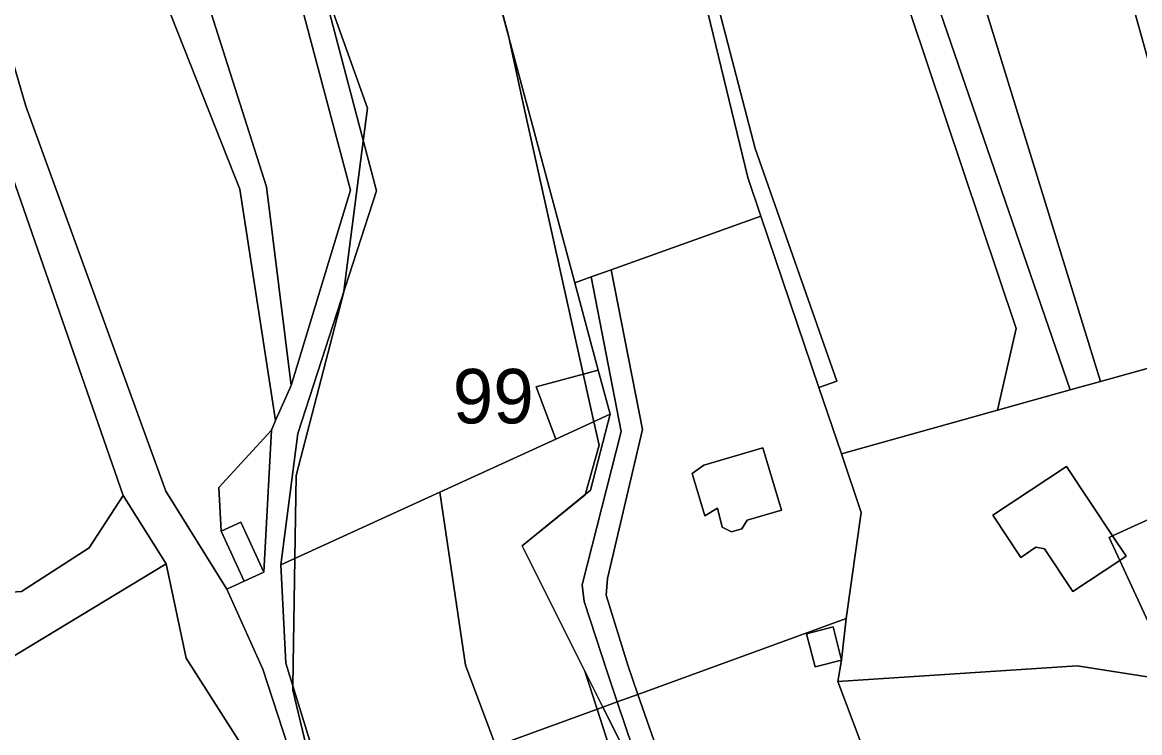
# Model space of a CAD drawing. Extents: x -502026 to -497664, y -1143484 to -1138019.
# Drawn here: x -498725.7 to -498561.6, y -1140123.3 to -1140018.9 of the extents above; entities that cross this region are included whole.
import ezdxf

# ---------------------------------------------------------------- set-up
doc = ezdxf.new("R2010")
doc.units = 0
for name, color, linetype in [('25', 7, 'Continuous'), ('31', 7, 'Continuous'), ('37', 7, 'Continuous'), ('43', 7, 'Continuous'), ('55', 7, 'Continuous'), ('62', 7, 'Continuous'), ('7', 7, 'Continuous')]:
    doc.layers.add(name, color=color, linetype=linetype)

msp = doc.modelspace()

# ---------------------------------------------------------------- linework, layer by layer
at = {"layer": '25'}
for points in [[(-498712.25, -1139972.61), (-498689.86, -1140043.06), (-498686.21, -1140072.24), (-498688.51, -1140077.4), (-498693.76, -1140043.4), (-498707.51, -1140008.59), (-498714.46, -1139986.58), (-498717.98, -1139975.42), (-498712.79, -1139970.57)], [(-498727.94, -1140039.32), (-498751.07, -1140049.89), (-498739.06, -1140080.19), (-498736.41, -1140103.23), (-498725.81, -1140102.53), (-498715.9, -1140096.1), (-498710.91, -1140088.4), (-498704.59, -1140098.48), (-498735.04, -1140116.85), (-498736.55, -1140110.23), (-498751.07, -1140095.02), (-498750.81, -1140092.61), (-498749.67, -1140082.31), (-498743.36, -1140080.78), (-498755.47, -1140046.68), (-498756.33, -1140044.28), (-498730, -1140033.28)], [(-498710.91, -1140088.4), (-498715.9, -1140096.1), (-498725.81, -1140102.53), (-498736.41, -1140103.23), (-498739.06, -1140080.19), (-498751.07, -1140049.89), (-498727.94, -1140039.32)]]:
    msp.add_lwpolyline(points, close=True, dxfattribs=at)
for points in [[(-498547.05, -1140117.17), (-498570.8, -1140113.45), (-498605.95, -1140115.74), (-498605.41, -1140112.59), (-498604.75, -1140106.51), (-498602.51, -1140090.92), (-498605.43, -1140082.3), (-498582.52, -1140075.89), (-498571.82, -1140072.9), (-498567.4, -1140071.66), (-498547.17, -1140066.02)], [(-498559.18, -1140091.38), (-498565.61, -1140094.35), (-498572.36, -1140084.16), (-498583.19, -1140091.32), (-498579.1, -1140097.52), (-498576.88, -1140096.03), (-498575.62, -1140096.27), (-498571.46, -1140102.52), (-498564.56, -1140097.96), (-498559.5, -1140108.89)]]:
    msp.add_lwpolyline(points, dxfattribs=at)
at = {"layer": '31'}
msp.add_lwpolyline([(-498674.75, -1140195.99), (-498680.38, -1140198.74), (-498683.99, -1140191.33), (-498699.81, -1140199.06), (-498713.39, -1140173.67), (-498729.52, -1140136.87), (-498735.04, -1140116.85), (-498704.59, -1140098.48), (-498701.66, -1140112.3), (-498691.1, -1140128.83), (-498682.3, -1140153.95)], close=True, dxfattribs=at)
at = {"layer": '37'}
for points in [[(-498580.7, -1139904.91), (-498574.32, -1139926.66), (-498559.71, -1139982.7), (-498534.68, -1140067.99), (-498523.51, -1140099.19), (-498525.46, -1140099.67), (-498503.51, -1140161.05), (-498513.07, -1140159.27), (-498523.05, -1140142.79), (-498532.36, -1140111.9), (-498543.21, -1140078.75), (-498547.17, -1140066.02), (-498557.89, -1140033.39), (-498577.39, -1139963.52), (-498584.01, -1139942.13), (-498590.01, -1139920.48), (-498609.44, -1139845.64), (-498615.65, -1139814.41), (-498623.41, -1139785.38), (-498626.05, -1139772.41), (-498623.42, -1139762.03), (-498619.31, -1139757.84), (-498592.84, -1139833.58), (-498587.99, -1139880.06)], [(-498590.01, -1139920.48), (-498584.01, -1139942.13), (-498596.15, -1139928.3), (-498610.66, -1139931.23), (-498567.4, -1140071.66), (-498571.82, -1140072.9), (-498605.77, -1139974.16), (-498614.84, -1139940.05), (-498617.87, -1139937.49), (-498639.91, -1139872.46), (-498644.26, -1139843.3), (-498642.74, -1139830.04), (-498633.26, -1139854.5), (-498613.18, -1139925.51)], [(-498672.63, -1139848.98), (-498663.63, -1139876.66), (-498638.19, -1139954.89), (-498627.01, -1140009.3), (-498619.17, -1140041.68), (-498617.24, -1140047.37), (-498639.25, -1140055.25), (-498642.18, -1140056.3), (-498644.57, -1140057.16), (-498671.08, -1139958.4), (-498663.04, -1139937.41), (-498672.5, -1139909.81), (-498683.31, -1139899.39), (-498702.08, -1139848.49), (-498674.5, -1139843.51)], [(-498582.52, -1140075.89), (-498605.43, -1140082.3), (-498608.73, -1140072.55), (-498606.09, -1140071.61), (-498618.07, -1140037.42), (-498625.5, -1140008.98), (-498627.01, -1140009.3), (-498638.19, -1139954.89), (-498663.63, -1139876.66), (-498644.2, -1139870.82), (-498621.06, -1139939.57), (-498617.75, -1139942.21), (-498605.69, -1139986.46), (-498579.78, -1140063.88)], [(-498584.01, -1139942.13), (-498577.39, -1139963.52), (-498557.89, -1140033.39), (-498547.17, -1140066.02), (-498567.4, -1140071.66), (-498610.66, -1139931.23), (-498596.15, -1139928.3)], [(-498608.73, -1140072.55), (-498605.43, -1140082.3), (-498602.51, -1140090.92), (-498604.75, -1140106.51), (-498635.31, -1140117.65), (-498636.81, -1140113.33), (-498639.97, -1140103.05), (-498639.77, -1140100.6), (-498634.64, -1140078.71), (-498639.25, -1140055.25), (-498617.24, -1140047.37)], [(-498638.34, -1140118.75), (-498640.44, -1140119.52), (-498652.29, -1140095.81), (-498642.28, -1140087.64), (-498639.38, -1140076.48), (-498641.13, -1140069.98), (-498644.57, -1140057.16), (-498642.18, -1140056.3), (-498637.78, -1140079.01), (-498643.5, -1140101.56), (-498643.21, -1140103.98), (-498639.8, -1140114.46)], [(-498635.31, -1140117.65), (-498638.34, -1140118.75), (-498639.8, -1140114.46), (-498643.21, -1140103.98), (-498643.5, -1140101.56), (-498637.78, -1140079.01), (-498642.18, -1140056.3), (-498639.25, -1140055.25), (-498634.64, -1140078.71), (-498639.77, -1140100.6), (-498639.97, -1140103.05), (-498636.81, -1140113.33)], [(-498616.95, -1140081.43), (-498625.63, -1140083.96), (-498627.33, -1140085.19), (-498625.5, -1140091.39), (-498623.62, -1140090.3), (-498622.92, -1140093.07), (-498621.56, -1140093.77), (-498620.03, -1140093.33), (-498619.26, -1140092.06), (-498614.24, -1140090.59)], [(-498605.41, -1140112.59), (-498606.65, -1140107.71), (-498610.56, -1140108.73), (-498609.27, -1140113.61), (-498605.41, -1140112.59), (-498605.95, -1140115.74), (-498598.07, -1140136.66), (-498625.77, -1140147.79), (-498626.21, -1140147.97), (-498626.85, -1140145.7), (-498630.48, -1140131.52), (-498633.99, -1140121.45), (-498635.31, -1140117.65), (-498604.75, -1140106.51)], [(-498547.05, -1140117.17), (-498544.9, -1140123.19), (-498553.52, -1140120.93), (-498556.27, -1140131.07), (-498546.77, -1140133.65), (-498545.8, -1140129.93), (-498543.71, -1140130.48), (-498542.85, -1140127.18), (-498544.93, -1140126.63), (-498544.09, -1140123.4), (-498544.9, -1140123.19), (-498532.69, -1140118.83), (-498526.12, -1140142.06), (-498518.02, -1140162.88), (-498520.94, -1140164.17), (-498530.79, -1140144.21), (-498571.63, -1140162.6), (-498560.56, -1140182.88), (-498581.76, -1140187.79), (-498588.51, -1140166.89), (-498590.01, -1140162.02), (-498598.07, -1140136.66), (-498605.95, -1140115.74), (-498570.8, -1140113.45)], [(-498632.83, -1140135.95), (-498634.63, -1140131.14), (-498640.44, -1140119.52), (-498638.34, -1140118.75), (-498637.06, -1140122.49), (-498633.7, -1140132.45)], [(-498626.21, -1140147.97), (-498629.39, -1140149.25), (-498630.23, -1140146.34), (-498630.69, -1140144.51), (-498630.44, -1140142.31), (-498632.83, -1140135.95), (-498633.7, -1140132.45), (-498637.06, -1140122.49), (-498638.34, -1140118.75), (-498635.31, -1140117.65), (-498633.99, -1140121.45), (-498630.48, -1140131.52), (-498626.85, -1140145.7)]]:
    msp.add_lwpolyline(points, close=True, dxfattribs=at)
at = {"layer": '43'}
msp.add_lwpolyline([(-498671.08, -1139958.4), (-498644.57, -1140057.16), (-498641.13, -1140069.98), (-498650.24, -1140072.45), (-498647.34, -1140080.12), (-498664.39, -1140087.93), (-498687.74, -1140098.62), (-498685.24, -1140079.33), (-498673.72, -1140043.63), (-498689.86, -1139982.26)], dxfattribs=at)
msp.add_lwpolyline([(-498639.38, -1140076.48), (-498647.34, -1140080.12), (-498650.24, -1140072.45), (-498641.13, -1140069.98)], close=True, dxfattribs=at)
at = {"layer": '55'}
for points in [[(-498605.77, -1139974.16), (-498571.82, -1140072.9), (-498582.52, -1140075.89), (-498579.78, -1140063.88), (-498605.69, -1139986.46)], [(-498736.26, -1139993.31), (-498725.17, -1140031.2), (-498704.65, -1140087.78), (-498695.68, -1140102.2), (-498690.38, -1140113.94), (-498677.05, -1140154.76), (-498679.25, -1140155.67), (-498672.29, -1140195.45), (-498674.75, -1140195.99), (-498682.3, -1140153.95), (-498691.1, -1140128.83), (-498701.66, -1140112.3), (-498704.59, -1140098.48), (-498710.91, -1140088.4), (-498727.94, -1140039.32), (-498730, -1140033.28), (-498745.48, -1139978.29)], [(-498689.86, -1139982.26), (-498673.72, -1140043.63), (-498685.24, -1140079.33), (-498687.74, -1140098.62), (-498686.99, -1140113.07), (-498670.1, -1140167.8), (-498666.59, -1140171.29), (-498668.01, -1140171.71), (-498667.14, -1140174.62), (-498673.37, -1140168.13), (-498677.05, -1140154.76), (-498690.38, -1140113.94), (-498695.68, -1140102.2), (-498693.11, -1140101), (-498690.24, -1140099.68), (-498689.13, -1140078.8), (-498688.51, -1140077.4), (-498686.21, -1140072.24), (-498677.51, -1140043.55), (-498693.22, -1139984.36)], [(-498670.1, -1140167.8), (-498686.99, -1140113.07), (-498687.74, -1140098.62), (-498664.39, -1140087.93), (-498660.64, -1140113.36), (-498656.19, -1140125.25)]]:
    msp.add_lwpolyline(points, dxfattribs=at)
for points in [[(-498608.73, -1140072.55), (-498617.24, -1140047.37), (-498619.17, -1140041.68), (-498627.01, -1140009.3), (-498625.5, -1140008.98), (-498618.07, -1140037.42), (-498606.09, -1140071.61)], [(-498640.44, -1140119.52), (-498656.19, -1140125.25), (-498660.64, -1140113.36), (-498664.39, -1140087.93), (-498647.34, -1140080.12), (-498639.38, -1140076.48), (-498642.28, -1140087.64), (-498652.29, -1140095.81)], [(-498532.36, -1140111.9), (-498534.86, -1140112.8), (-498532.69, -1140118.83), (-498544.9, -1140123.19), (-498547.05, -1140117.17), (-498550.14, -1140110.9), (-498552.56, -1140105.68), (-498559.5, -1140108.89), (-498564.56, -1140097.96), (-498563.63, -1140097.35), (-498565.61, -1140094.35), (-498559.18, -1140091.38), (-498557.32, -1140090.52), (-498559.32, -1140086.21), (-498547.64, -1140080.8), (-498543.21, -1140078.75)], [(-498616.95, -1140081.43), (-498614.24, -1140090.59), (-498619.26, -1140092.06), (-498620.03, -1140093.33), (-498621.56, -1140093.77), (-498622.92, -1140093.07), (-498623.62, -1140090.3), (-498625.5, -1140091.39), (-498627.33, -1140085.19), (-498625.63, -1140083.96)], [(-498565.61, -1140094.35), (-498566.12, -1140094.59), (-498564.56, -1140097.96), (-498571.46, -1140102.52), (-498575.62, -1140096.27), (-498576.88, -1140096.03), (-498579.1, -1140097.52), (-498583.19, -1140091.32), (-498572.36, -1140084.16)], [(-498690.24, -1140099.68), (-498693.11, -1140101), (-498696.5, -1140093.65), (-498693.62, -1140092.32)], [(-498564.56, -1140097.96), (-498566.12, -1140094.59), (-498565.61, -1140094.35), (-498563.63, -1140097.35)], [(-498605.41, -1140112.59), (-498609.27, -1140113.61), (-498610.56, -1140108.73), (-498606.65, -1140107.71)], [(-498632.83, -1140135.95), (-498630.69, -1140144.51), (-498631.31, -1140150.02), (-498644.88, -1140155.47), (-498656.19, -1140125.25), (-498640.44, -1140119.52), (-498634.63, -1140131.14)]]:
    msp.add_lwpolyline(points, close=True, dxfattribs=at)
at = {"layer": '62'}
for points in [[(-498635, -1140139.5), (-498641.29, -1140119.83), (-498643.09, -1140114.22), (-498652.29, -1140095.81), (-498643.08, -1140088.3), (-498641, -1140081), (-498641.76, -1140077.57), (-498652, -1140031.5), (-498654.37, -1140020.63), (-498659.91, -1140000)], [(-498659.91, -1140000), (-498654.37, -1140020.63), (-498652, -1140031.5), (-498641.76, -1140077.57), (-498641, -1140081), (-498643.08, -1140088.3), (-498652.29, -1140095.81), (-498643.09, -1140114.22), (-498641.29, -1140119.83), (-498635, -1140139.5)], [(-498682.18, -1140011.46), (-498675, -1140031.5), (-498675.63, -1140036.36), (-498678.49, -1140058.4), (-498678.5, -1140058.5), (-498685.5, -1140085.5), (-498685.69, -1140097.68), (-498685.99, -1140116.31), (-498686, -1140117), (-498679.5, -1140144)], [(-498679.5, -1140144), (-498686, -1140117), (-498685.99, -1140116.31), (-498685.69, -1140097.68), (-498685.5, -1140085.5), (-498678.5, -1140058.5), (-498678.49, -1140058.4), (-498675.63, -1140036.36), (-498675, -1140031.5), (-498682.18, -1140011.46)]]:
    msp.add_lwpolyline(points, dxfattribs=at)
at = {"layer": '7'}
for points in [[(-498686.21, -1140072.24), (-498689.86, -1140043.06), (-498712.25, -1139972.61), (-498693.22, -1139984.36), (-498677.51, -1140043.55)], [(-498688.51, -1140077.4), (-498689.13, -1140078.8), (-498696.84, -1140087.24), (-498696.5, -1140093.65), (-498693.11, -1140101), (-498695.68, -1140102.2), (-498704.65, -1140087.78), (-498725.17, -1140031.2), (-498736.26, -1139993.31), (-498724.44, -1139989.66), (-498714.46, -1139986.58), (-498707.51, -1140008.59), (-498693.76, -1140043.4)], [(-498690.24, -1140099.68), (-498693.62, -1140092.32), (-498696.5, -1140093.65), (-498696.84, -1140087.24), (-498689.13, -1140078.8)]]:
    msp.add_lwpolyline(points, close=True, dxfattribs=at)

# ---------------------------------------------------------------- texts
at = {"layer": '62'}
msp.add_text('99', height=8, dxfattribs=at).set_placement((-498662.5, -1140077.82))

doc.saveas('drawing.dxf')
